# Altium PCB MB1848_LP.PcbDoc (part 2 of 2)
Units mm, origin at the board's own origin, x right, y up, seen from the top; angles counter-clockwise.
Board outline 61.5 x 34 mm, 4 copper layers (Top Layer, MidLayer 1, MidLayer 2, Bottom Layer), stack 1.035 mm thick; 72 components, 64 nets, 238 pads, 1060 vias.
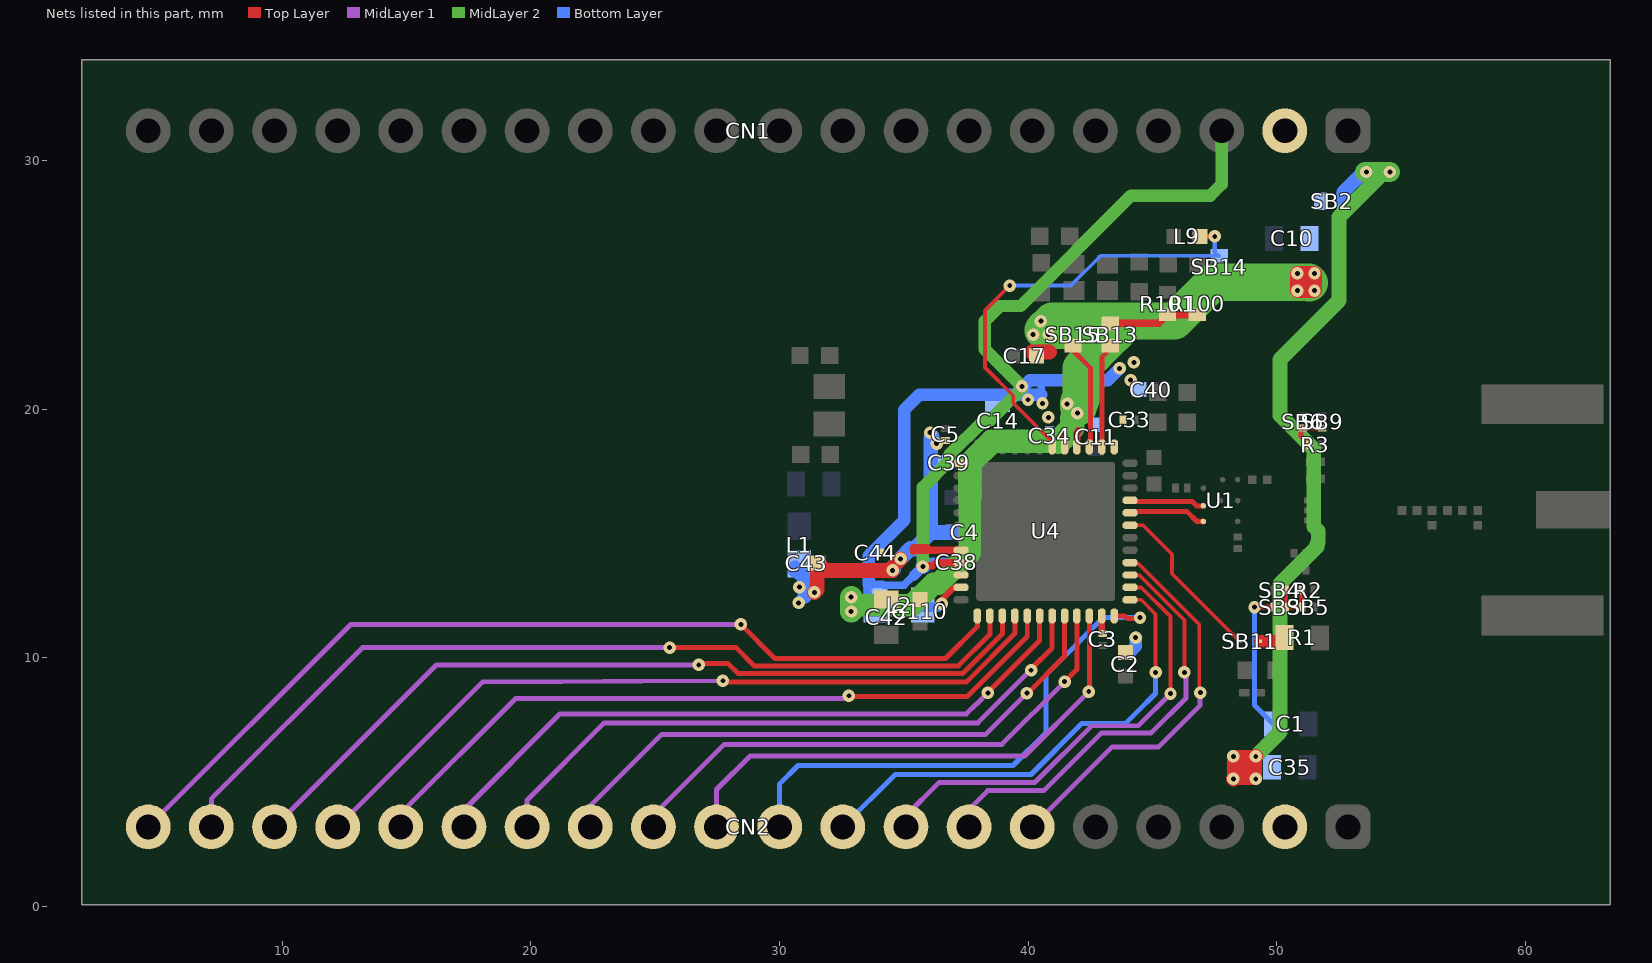
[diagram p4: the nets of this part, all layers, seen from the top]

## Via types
v1: diameter 0.4, hole 0.2, Top Layer to Bottom Layer, 477 vias
v2: diameter 0.65, hole 0.2, Top Layer to Bottom Layer, 317 vias
v3: diameter 0.5, hole 0.2, Top Layer to Bottom Layer, 189 vias
v4: diameter 0.4, hole 0.2, Top Layer to Bottom Layer, tented both sides, 77 vias

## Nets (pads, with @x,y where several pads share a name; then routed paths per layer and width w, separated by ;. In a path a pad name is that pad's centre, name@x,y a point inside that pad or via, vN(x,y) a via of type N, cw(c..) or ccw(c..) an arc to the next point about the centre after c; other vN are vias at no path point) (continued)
NetCN2_6: CN2.6 U4.16 | length 15.9
  Top Layer w0.15: U4.16@44.099,13.824 44.143,13.78 44.437,13.78 46.883,11.333 v3@46.883,8.632
  Top Layer w0.2: v3@46.883,8.632 46.883,8.551 46.903,8.532 46.903,8.571 v3(46.923,8.592)
  MidLayer 1 w0.2: CN2.6@40.163,3.192 43.386,6.414 45.248,6.414 46.903,8.07 v3@46.903,8.552
NetCN2_7: CN2.7 U4.15 | length 17.4
  Top Layer w0.15: U4.15@44.099,13.324 44.114,13.309 44.478,13.309 46.283,11.504 v3(46.283,9.41)
  MidLayer 1 w0.2: CN2.7@37.623,3.192 37.623,3.902 38.368,4.646 40.628,4.646 42.941,6.959 44.934,6.959 46.346,8.371 46.346,9.348 v3(46.283,9.41)
NetCN2_8: CN2.8 U4.14 | length 18.3
  Top Layer w0.15: U4.14@44.099,12.824 44.551,12.824 45.723,11.651 v3(45.723,8.552)
  MidLayer 1 w0.2: CN2.8@35.083,3.192 35.083,3.646 36.42,4.983 40.274,4.983 42.549,7.259 44.431,7.259 v3(45.723,8.552)
NetCN2_9: CN2.9 U4.13 | length 19.3
  Top Layer w0.15: U4.13@44.099,12.324 44.543,12.324 45.123,11.743 v3(45.123,9.41)
  Bottom Layer w0.2: CN2.9@32.543,3.192 34.653,5.301 36.314,5.301 cw(c36.349,5.054) 36.384,5.301 40.111,5.301 42.165,7.354 43.923,7.354 44.372,7.804 45.123,8.555 v3(45.123,9.41)
NetCN2_10: CN2.10 U4.12 | length 21.5
  Top Layer w0.2: U4.12@43.461,11.677 43.878,11.677 43.99,11.565 44.451,11.565 v3(44.498,11.611)
  Bottom Layer w0.2: CN2.10@30.003,3.192 30.003,4.927 30.74,5.663 39.39,5.663 40.722,6.996 40.722,9.311 43.023,11.611 v3(44.498,11.611)
NetCN2_11: CN2.11 U4.10 | length 21.2
  Top Layer w0.2: v3(42.435,8.63) 42.461,8.657 U4.10@42.461,11.677
  MidLayer 1 w0.2: CN2.11@27.463,3.192 27.463,4.695 28.814,6.046 39.85,6.046 v3(42.435,8.63)
NetCN2_12: CN2.12 U4.9 | length 22.1
  Top Layer w0.2: v3(41.466,9.032) 41.961,9.528 U4.9@41.961,11.677
  MidLayer 1 w0.2: CN2.12@24.923,3.192 24.923,3.659 27.774,6.509 38.942,6.509 v3(41.466,9.032)
NetCN2_13: CN2.13 U4.8 | length 24
  Top Layer w0.2: v3(39.943,8.572) 39.983,8.572 41.461,10.05 U4.8@41.461,11.677
  MidLayer 1 w0.2: CN2.13@22.383,3.192 22.383,4.038 25.26,6.914 38.286,6.914 v3(39.943,8.572)
NetCN2_14: CN2.14 U4.7 | length 26
  Top Layer w0.2: v3(40.115,9.492) 40.115,9.544 40.961,10.39 U4.7@40.961,11.677
  MidLayer 1 w0.2: CN2.14@19.843,3.192 19.843,4.27 22.953,7.379 37.971,7.379 v3@40.099,9.508
NetCN2_15: CN2.15 U4.6 | length 28.2
  Top Layer w0.15: U4.6@40.421,11.637 U4.6@40.461,11.677 U4.6@40.461,11.427
  Top Layer w0.2: v3@38.363,8.532 v3@38.403,8.572 ; v3@38.443,8.572 v3@38.403,8.572 ; U4.6@40.463,11.752 40.463,11.677 40.463,11.637 40.463,11.427 40.463,10.692 38.363,8.592 v3(38.373,8.582) 38.383,8.572 v3@38.403,8.572
  MidLayer 1 w0.2: CN2.15@17.303,3.192 17.303,3.872 21.168,7.737 37.514,7.737 37.91,8.133 37.925,8.133 v3(38.373,8.582)
NetCN2_16: CN2.16 U4.5 | length 29.5
  Top Layer w0.2: v3@32.791,8.435 37.55,8.435 39.944,10.83 39.961,10.83 U4.5@39.961,11.677
  MidLayer 1 w0.2: CN2.16@14.763,3.192 14.763,3.738 19.383,8.357 32.674,8.357 v3(32.784,8.467)
NetCN2_17: CN2.17 U4.4 | length 31.2
  Top Layer w0.2: v3(27.722,9.069) 27.779,9.012 27.988,9.012 ; 27.989,9.011 37.503,9.011 39.461,10.97 U4.4@39.461,11.677
  MidLayer 1 w0.2: CN2.17@12.223,3.192 18.058,9.027 v3(27.722,9.069)
NetCN2_18: CN2.18 U4.3 | length 33.5
  Top Layer w0.2: v3(26.749,9.709) 26.794,9.755 27.934,9.755 28.324,9.365 32.297,9.365 32.299,9.367 37.375,9.367 38.961,10.953 U4.3@38.961,11.677
  MidLayer 1 w0.2: CN2.18@9.683,3.192 16.199,9.707 v3(26.749,9.709)
NetCN2_19: CN2.19 U4.2 | length 36.5
  Top Layer w0.2: v3(25.577,10.398) 28.25,10.398 28.983,9.665 32.173,9.665 32.175,9.667 37.19,9.667 38.461,10.938 U4.2@38.461,11.677
  MidLayer 1 w0.2: CN2.19@7.143,3.192 7.143,4.321 13.22,10.398 v3(25.577,10.398)
NetCN2_20: CN2.20 U4.1 | length 38.3
  Top Layer w0.2: v3(28.438,11.338) 29.811,9.965 32.049,9.965 32.05,9.967 33.169,9.967 ; 33.215,9.972 cw(c33.169,10.167) 33.169,9.967 ; U4.1@37.954,11.677 37.954,11.245 36.676,9.967 33.169,9.967
  MidLayer 1 w0.2: CN2.20@4.603,3.192 12.739,11.328 28.428,11.328 v3(28.438,11.338)
NetL2_2: L2.2 U4.47 | length 2
  Top Layer w0.25: v3(36.523,12.172) 36.523,12.331 37.015,12.824 U4.47@37.302,12.824
  Bottom Layer w0.4: L2.2@35.776,12.032 36.366,12.032 v3@36.543,12.209
NetL9_2: L9.2 SB14.1 U4.30 | length 18.4
  Top Layer w0.15: v3(39.258,24.965) 38.26,23.967 38.26,21.665 39.394,20.531 39.394,20.247 40.961,18.68 U4.30@40.961,18.474
  Top Layer w0.2: L9.2@46.963,26.942 v3(47.503,26.942)
  Bottom Layer w0.15: v3(39.258,24.965) 41.71,24.965 42.914,26.169 SB14.1@47.678,26.169 cw(c47.678,26.343) SB14.1@47.503,26.343
  Bottom Layer w0.2: SB14.1@47.503,26.343 v3(47.503,26.942)
NetR1_2: R1.2 SB11.1 | length 1
  Top Layer w0.5: SB11.1@49.328,10.661 50.172,10.661 R1.2@50.303,10.792
NetR2_2: R2.2 SB3.2 SB4.2 SB5.2 | length 2
  Top Layer w0.2: SB4.2@50.357,12.718 SB3.2@50.357,12.034 50.359,12.035 SB5.2@51.022,12.035 R2.2@51.022,12.72
NetR3_2: R3.2 SB6.2 SB9.2 | length 1.8
  Top Layer w0.2: SB6.2@51.041,19.24 SB6.2@50.986,19.24 ; SB6.2@51.041,19.27 SB6.2@51.029,19.283 ; R3.2@51.312,18.566 50.976,18.901 50.976,19.23 SB6.2@50.986,19.24 ; SB9.2@51.832,19.24 51.072,19.24 SB6.2@51.029,19.283 ; SB6.2@50.986,19.24 SB6.2@51.029,19.283
NetR100_1: R100.1 R101.1 SB13.2 | length 3.8
  Top Layer w0.2: SB13.2@43.303,23.442 SB13.2@43.403,23.542
  Top Layer w0.3: SB13.2@43.303,23.442 45.253,23.442 R101.1@45.603,23.792 R100.1@46.803,23.792
NetSB11_2: SB11.2 U4.19 | length 6.8
  Top Layer w0.15: U4.19@44.099,15.324 44.614,15.324 45.783,14.155 45.783,13.372 48.163,10.992 48.172,10.992 SB11.2@48.503,10.661
NetSB13_1: SB13.1 U4.26 | length 4.1
  Top Layer w0.2: U4.26@42.961,18.474 42.961,22.089 SB13.1@43.303,22.431
NetSB14_2: SB14.2
NetSB15_1: SB15.1 U4.27 | length 4.2
  Top Layer w0.2: SB15.1@41.803,22.352 42.513,21.642 42.513,18.525 U4.27@42.461,18.474
RFI_N: U1.3 U4.21 | length 3
  Top Layer w0.2: U4.21@44.145,16.286 46.59,16.286 46.771,16.105 U1.3@47.048,16.105
RFI_P: U1.2 U4.20 | length 3.1
  Top Layer w0.2: U4.20@44.133,15.873 46.395,15.873 46.791,15.477 U1.2@47.028,15.476
  Top Layer w0.22: U1.2@47.028,15.476 U1.2@47.035,15.469
VDD: C1.2 C2.2 C3.2 C4.2 C5.2 C35.2 C39.1 C43.2 C44.2 CN2.2 L1.1 SB2.1 SB3.1 U4.11 U4.37 U4.44 | length 56.9
  Top Layer w0.2: v3@49.11,12.036 49.112,12.034 SB3.1@49.877,12.034
  Top Layer w0.254: C3.2@42.963,11.072 U4.11@42.963,11.635
  Top Layer w0.3: 35.373,14.279 35.418,14.324 ; 35.817,14.384 35.948,14.384 36.009,14.324 U4.44@37.302,14.324
  Top Layer w0.4: 35.413,14.367 35.931,14.367
  Top Layer w0.5: v3(48.253,5.125) v3(48.253,6.025) v3(49.153,6.025) v3(49.153,5.125) v3(48.253,5.125)
  Top Layer w0.6: v3(31.401,12.621) 31.514,12.735 31.514,13.372 ; C43.2@31.546,13.802 31.839,13.51 v3(34.549,13.51) 34.549,13.649 v3(34.87,13.971) ; v3(48.253,5.125) v3(49.153,6.025)
  MidLayer 2 w0.6: v3(49.153,6.025) 50.131,7.004 50.131,12.972 51.611,14.452 51.611,14.578 51.665,14.632 51.665,15.087 51.635,15.117 51.635,15.129 51.486,15.278 51.486,18.388 50.128,19.746 50.128,21.993 52.503,24.368 52.503,27.72 54.097,29.314 54.097,29.535
  MidLayer 2 w0.8: v3@53.546,29.535 v3@54.546,29.535
  Bottom Layer w0.2: v3(49.103,12.034) 49.103,8.085 C1.2@49.856,7.332
  Bottom Layer w0.45: C4.2@36.955,15.035 C4.2@36.968,15.048
  Bottom Layer w0.5: 44.026,10.152 44.321,10.447 v3(44.321,10.802)
  Bottom Layer w0.55: SB2.1@52.668,28.363 52.668,28.719 v3@53.483,29.533
  Bottom Layer w0.6: L1.1@30.614,13.529 30.614,13.604 31.023,13.195 31.023,12.47 ; v3(34.549,13.51) 34.549,13.519 34.592,13.562 34.592,13.693 v3(34.87,13.971) 34.87,13.991 35.266,14.386 ; 35.413,14.367 36.081,15.035 ; v3@36.134,18.901 36.081,18.848 36.081,15.035 ; C4.2@36.955,15.035 36.081,15.035
  Bottom Layer w0.8: v3(53.602,29.533) v3@54.294,29.533
  other v3: 30.769,12.198 30.795,12.839 36.313,18.604 36.052,19.052 54.544,29.533
VDDPA: C14.1 C33.2 C34.2 C38.1 C40.1 L2.1 U4.25 U4.29 U4.45 | length 51.2
  Top Layer w0.3: v3(35.763,13.658) 35.801,13.696 36.163,13.696 36.291,13.824 U4.45@37.302,13.824 ; U4.29@41.461,18.474 41.461,18.826
  MidLayer 2 w0.4: v3@39.606,20.909 v3(39.751,20.909)
  MidLayer 2 w0.5: v3(35.763,13.658) 35.763,16.847 36.821,17.905 36.821,18.146 38.196,19.521 38.437,19.521 39.751,20.835 v3(39.751,20.909) 38.26,22.4 38.26,22.582 38.256,22.585 38.256,23.082 38.26,23.086 38.26,23.541 38.863,24.144 39.701,24.144 44.136,28.58 47.322,28.58 47.783,29.041 47.783,31.192
  Bottom Layer w0.3: L2.1@33.851,12.112 33.552,12.411 33.552,12.947 33.585,12.947 34.156,12.947 34.193,12.91 35.006,12.91 35.006,12.924 35.412,13.329 ; v3@35.712,13.658 v3(35.763,13.658) ; v3@35.782,13.677 v3(35.763,13.658) ; v3@35.817,13.658 v3(35.763,13.658) ; 40.531,20.579 40.531,21.038 40.573,21.08
  Bottom Layer w0.4: 35.412,13.329 35.412,13.309 35.375,13.273 35.378,13.273 v3(35.763,13.658) ; v3@35.782,13.677 35.942,13.837 C38.1@36.742,13.837
  Bottom Layer w0.5: 33.585,12.947 33.585,14.099 35.01,15.524 35.01,19.959 35.616,20.565 36.145,20.565 36.159,20.579 40.531,20.579 ; v3@39.804,20.899 40.068,21.163 43.206,21.163 v3(43.674,21.631)
  Bottom Layer w0.6: v3(35.763,13.658) v3@35.782,13.677
  other v3: 40.809,19.664 40.576,20.228 39.991,20.373 44.118,21.161 44.247,21.875
VDDRF: C10.1 C11.1 C17.1 C42.1 C110.1 CN1.2 SB2.2 U4.28 U4.46 | length 37.8
  Top Layer w0.3: U4.46@37.302,13.324 U4.46@37.312,13.324 ; U4.28@41.961,18.474 41.961,19.033 42.005,19.077 42.005,19.131
  Top Layer w0.6: C17.1@40.152,22.3 40.852,22.3 ; v3(50.823,25.454) v3(51.515,25.454) ; v3@50.823,25.455 v3(50.823,24.764) ; 51.312,25.253 v3(50.823,24.764) ; v3@51.515,25.455 v3(51.515,24.764) v3(50.823,24.764)
  MidLayer 2 w0.9: v3(32.877,11.854) v3(32.877,12.434) ; 33.153,12.112 35.332,12.112 36.192,12.972 36.393,12.972 37.646,14.224 37.646,16.448
  MidLayer 2 w0.95: 37.646,16.448 37.646,16.904 ; 37.646,17.12 37.646,17.804 38.538,18.696 41.21,18.696
  MidLayer 2 w1: 41.21,18.696 41.222,18.696 41.236,18.709 41.238,18.709 41.269,18.741 41.278,18.741 41.293,18.756 41.295,18.756 41.752,19.213 41.752,19.235 41.769,19.252 41.769,19.625
  MidLayer 2 w1.5: v3@42.019,20.079 42.019,20.26 42.123,20.364 42.123,21.635 42.738,22.25 42.738,22.26 43.383,22.905 43.394,22.905 43.653,23.164 40.593,23.164 40.966,23.537 45.882,23.537 47.441,25.096 51.28,25.096 51.3,25.076
  Bottom Layer w0.6: CN1.2@50.323,31.192 CN1.2@50.323,31.414
  other v3: 41.98,19.836 41.568,20.206 40.196,22.994 40.821,22.994 40.507,23.531
pads on no net: U4.23
copper on no net: | length 1464.4
  Top Layer w0.381: 94.787,1.818 105.199,1.818 128.814,1.818 158.016,1.818 174.522,1.818 188.996,1.818 ; 94.787,4.866 105.199,4.866 128.814,4.866 158.016,4.866 174.522,4.866 188.996,4.866 ; 94.787,7.914 105.199,7.914 128.814,7.914 158.016,7.914 174.522,7.914 188.996,7.914 ; 94.787,10.962 105.199,10.962 128.814,10.962 158.016,10.962 174.522,10.962 188.996,10.962 ; 94.787,14.01 105.199,14.01 128.814,14.01 158.016,14.01 174.522,14.01 188.996,14.01 ; 94.787,17.058 105.199,17.058 128.814,17.058 158.016,17.058 174.522,17.058 188.996,17.058 ; 94.787,20.106 105.199,20.106 128.814,20.106 158.016,20.106 174.522,20.106 188.996,20.106 ; 94.787,23.154 105.199,23.154 128.814,23.154 158.016,23.154 174.522,23.154 188.996,23.154 ; 94.787,26.202 105.199,26.202 128.814,26.202 158.016,26.202 174.522,26.202 188.996,26.202 ; 94.787,29.25 105.199,29.25 128.814,29.25 158.016,29.25 174.522,29.25 188.996,29.25 ; 94.787,32.298 188.996,32.298 ; 105.199,35.346 105.199,-1.23 ; 128.814,35.346 128.814,-1.23 ; 158.016,35.346 158.016,-1.23 ; 174.522,35.346 174.522,-1.23 ; 105.199,-1.23 128.814,-1.23 ; 105.199,-1.23 94.787,-1.23 94.787,35.346 188.996,35.346 188.996,-1.23 174.522,-1.23 ; 128.814,-1.23 158.016,-1.23 ; 158.016,-1.23 174.522,-1.23
  Bottom Layer w0.15: 32.543,31.192 32.543,28.586 36.637,24.492 42.065,24.492 43.343,25.77 46.549,25.77 47.051,25.269 47.678,25.269

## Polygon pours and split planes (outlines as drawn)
VDD on MidLayer 2 "NONET_L-01_P-001" (solid, pour order 33): 51.542,1.922 51.542,5.686 ccw(c50.812,5.686) 51.328,6.202 46.658,10.872 ccw(c46.248,10.462) 46.248,11.042 42.724,11.042 32.958,11.042 cw(c32.958,12.079) 31.921,12.079 31.921,12.256 cw(c32.654,12.256) 32.654,12.989 34.084,12.989 ccw(c34.084,14.226) 35.322,14.227 35.322,17.276 36.578,18.532 ccw(c36.29,18.82) 36.578,19.108 36.009,19.677 ccw(c35.531,19.2) 35.052,19.677 29.498,14.124 ccw(c30.249,13.373) 29.187,13.373 29.187,8.108 ccw(c29.931,8.108) 29.405,7.582 30.795,6.192 ccw(c31.287,6.685) 31.287,5.988 44.296,5.988 cw(c44.296,4.947) 45.027,5.689 46.064,4.669 ccw(c46.339,4.948) 46.339,4.556 48.082,4.556 cw(c48.082,4.069) 48.451,4.386 48.77,4.015 cw(c48.282,3.595) 48.926,3.595 48.926,1.922
GND on MidLayer 2 "TOP_LAYER_GND" (solid, remove dead copper, pour order 34): 1.97,34.244 63.467,34.244 63.467,0.056 1.97,0.056
GND on Top Layer "TOP_LAYER_GND" (solid, remove dead copper, pour order 30): 1.922,34.244 63.467,34.244 63.467,0.056 1.922,0.056
GND on MidLayer 1 "NONET_L-01_P-001" (solid, pour order 31): 1.932,0.056 63.43,0.056 63.43,34.269 1.932,34.269
GND on Bottom Layer "GND_L04_P035" (solid, remove dead copper, pour order 35): 1.97,34.244 63.467,34.244 63.467,0.056 1.97,0.056

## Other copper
Top Layer:
  region net VDD: 35.213,14.02 35.318,14.02 ccw(c35.318,14.586) 35.718,14.186 35.413,14.367
  region net VDDRF: 32.724,12.804 34.881,12.804 ccw(c34.881,15.615) 36.142,13.102 36.722,13.393 cw(c37.048,12.745) 37.048,13.471 37.391,13.471 37.391,13.181 37.162,13.181 ccw(c37.161,12.624) 36.82,13.064 35.371,11.989 33.773,11.989 33.547,11.675 cw(c33.23,11.902) 33.23,11.512 32.706,11.512 cw(c32.706,11.661) 32.558,11.661 32.558,12.637 cw(c32.724,12.637)
  region net VDD: 31.245,11.887 30.68,11.887 cw(c30.68,12.141) 30.426,12.141 30.426,12.958 cw(c30.745,12.958) 30.745,13.277 31.439,13.277 cw(c31.439,12.967) 31.75,12.967 31.75,12.569 cw(c31.323,12.569) 31.625,12.268
  region net VDDPA: 39.521,21.078 ccw(c39.748,20.93) 39.556,20.739 39.64,20.655 39.713,20.366 ccw(c40.048,20.451) 39.81,20.199 41.372,18.72 41.608,18.72 41.608,18.848 ccw(c41.039,18.849) 41.441,19.252 41.305,19.387 cw(c41.535,19.617) 41.21,19.617 41.21,19.649 41.21,19.733 ccw(c40.111,19.734) 40.888,20.511 40.354,21.045 ccw(c39.909,20.601) 39.909,21.229 39.799,21.229 ccw(c39.799,20.897)
  region net VDDRF: 41.806,18.772 41.806,19.207 ccw(c40.838,19.207) 41.523,19.892 41.355,20.059 cw(c41.475,20.179) 41.306,20.179 41.306,20.26 cw(c41.444,20.26) 41.346,20.358 41.421,20.433 cw(c41.502,20.352) 41.502,20.467 41.637,20.467 cw(c41.638,20.153) 41.86,20.375 42.191,20.044 cw(c42.072,19.925) 42.24,19.925 42.24,19.116 cw(c41.739,19.116) 42.177,18.872 42.121,18.772
  region net VDDRF: 41.409,20.003 41.36,20.053 cw(c41.515,20.209) 41.295,20.209 41.295,20.279 ccw(c40.858,20.279) 41.167,20.588 40.045,21.71 cw(c40.518,22.183) 39.849,22.183 39.849,23.415 cw(c40.324,23.415) 40.324,23.89 40.747,23.89 cw(c40.747,23.42) 41.216,23.42 41.216,22.002 ccw(c42.068,22.002) 41.466,21.399 41.878,20.988 cw(c41.528,20.637) 42.023,20.637 42.023,19.836
  region net VDD: 42.828,10.826 42.828,11.114 43.233,11.114 44.333,11.114 cw(c44.333,10.792) 44.656,10.792 44.656,10.039 cw(c43.955,10.038) 44.64,9.889 43.605,9.889 43.603,10.456 ccw(c43.3,10.455) 43.418,10.734 43.2,10.826
  region net VDD: 37.302,17.68 36.755,17.68 35.824,18.61 cw(c36.047,18.834) 35.731,18.834 35.731,19.206 cw(c35.927,19.206) 35.927,19.402 36.107,19.402 cw(c36.107,19.187) 36.322,19.187 36.322,18.994 36.438,18.878 36.866,18.878 37.24,18.504 cw(c37.091,18.355) 37.302,18.355
  region net VDDPA: 43.313,18.389 43.313,21.431 cw(c43.929,21.431) 43.521,21.893 43.751,22.096 cw(c43.928,21.896) 43.928,22.163 44.627,22.163 cw(c44.627,22.051) 44.739,22.051 44.739,21.718 cw(c44.087,21.718) 44.613,21.332 44.416,21.063 ccw(c44.563,20.773) 44.273,20.92 44.031,20.538 43.96,19.832 43.96,19.337 43.615,18.992 43.615,18.398
  pour cut-out: 44.873,18.925 44.86,18.938 44.672,19.056 44.672,19.139 44.86,19.327 46.909,19.327 46.909,18.938 44.873,18.938 44.848,18.964
  pour cut-out: 44.882,19.798 44.869,19.811 44.681,19.928 44.681,20.012 44.869,20.2 46.917,20.2 46.917,19.811 44.882,19.811 44.856,19.837
  pour cut-out: 43.96,19.832 44.16,19.832 44.166,19.838 44.166,19.283 44.014,19.283 43.96,19.337
  region net GND: 43.503,25.142 45.203,25.142 45.403,24.942 45.403,24.342 44.903,24.342 43.803,24.342 43.703,24.442 43.503,24.442
  pour cut-out: 31.343,20.372 32.643,20.372 32.643,19.872 31.343,19.872
  pour cut-out: 46.003,26.242 46.503,26.242 46.503,25.542 46.403,25.442 46.003,25.442
  pour cut-out: 46.203,27.342 46.603,27.342 46.603,26.542 46.203,26.542
  pour cut-out: 40.903,27.342 41.403,27.342 41.403,26.442 41.303,26.542 40.903,26.542
  pour cut-out: 49.266,9.954 49.328,9.892 49.703,9.892 49.703,9.092 49.203,9.092
  pour cut-out: 37.523,18.232 43.843,18.232 43.783,18.172 43.783,11.952 38.123,11.952 38.123,12.532 37.523,12.532
  region net VDD: 33.963,14.397 34.113,14.547 35.295,14.547 35.566,14.276 34.597,13.307 33.963,13.307
  region net NetC28_2: 58.443,15.919 59.132,16.688 60.782,16.688 60.782,15.194 59.093,15.194
  pour cut-out: 41.863,18.692 41.863,20.892 39.543,23.212 39.543,27.692 40.703,27.692 47.603,27.692 47.603,25.992 47.603,23.192 47.103,22.592 44.963,22.592 43.423,21.052 43.423,19.012 43.103,18.692
  pour cut-out: 45.16,17.299 47.516,17.299 47.516,15.012 45.16,15.012
  pour cut-out: 44.399,17.866 46.864,17.866 46.864,17.297 44.399,17.297
  region net NetC19_2: 49.012,17.013 48.858,17.013 48.426,17.158 48.858,17.303 49.012,17.303
  region net NetC25_1: 54.961,15.744 54.837,15.744 54.328,15.919 54.838,16.094 54.961,16.094
  region net NetC19_1: 49.711,17.333 49.83,17.333 50.166,17.076 49.801,16.983 49.711,16.983
  pour cut-out: 63.516,14.184 59.037,14.184 59.037,17.712 63.516,17.712
  pour cut-out: 58.536,16.273 59.036,17.704 59.036,16.286 59.024,16.273
  pour cut-out: 58.533,15.583 59.046,15.583 59.046,14.157 58.52,15.596
  text "Layer" at 96.565,33.06 h1.52
  text "Name" at 106.977,33.06 h1.52
  text "Material" at 130.592,33.06 h1.52
  text "Thickness" at 159.794,33.06 h1.52
  text "Constant" at 176.3,33.06 h1.52
  text "Top Overlay" at 106.977,30.012 h1.52
  text "Top Solder" at 106.977,26.964 h1.52
  text "Solder Resist" at 130.592,26.964 h1.52
  text "0.39mil" at 159.794,26.964 h1.52
  text "3.5" at 176.3,26.964 h1.52
  text "1" at 96.565,23.916 h1.52
  text "Top Layer" at 106.977,23.916 h1.52
  text "1.38mil" at 159.794,23.916 h1.52
  text "Dielectric 2" at 106.977,20.868 h1.52
  text "1 x 2116 + 1 x 106" at 130.592,20.868 h1.52
  text "6.30mil" at 159.794,20.868 h1.52
  text "3.7" at 176.3,20.868 h1.52
  text "2" at 96.565,17.82 h1.52
  text "MidLayer 1" at 106.977,17.82 h1.52
  text "0.69mil" at 159.794,17.82 h1.52
  text "Dielectric 1" at 106.977,14.772 h1.52
  text "FR-4" at 130.592,14.772 h1.52
  text "24.02mil" at 159.794,14.772 h1.52
  text "5" at 176.3,14.772 h1.52
  text "3" at 96.565,11.724 h1.52
  text "MidLayer 2" at 106.977,11.724 h1.52
  text "0.69mil" at 159.794,11.724 h1.52
  text "Dielectric 3" at 106.977,8.676 h1.52
  text "1 x 2116 + 1 x 106" at 130.592,8.676 h1.52
  text "6.30mil" at 159.794,8.676 h1.52
  text "3.7" at 176.3,8.676 h1.52
  text "4" at 96.565,5.628 h1.52
  text "Bottom Layer" at 106.977,5.628 h1.52
  text "1.38mil" at 159.794,5.628 h1.52
  text "Bottom Solder" at 106.977,2.58 h1.52
  text "Solder Resist" at 130.592,2.58 h1.52
  text "0.39mil" at 159.794,2.58 h1.52
  text "3.5" at 176.3,2.58 h1.52
  text "Bottom Overlay" at 106.977,-0.468 h1.52
  text ".Layer_Name" at 11.222,-22.076 h3
  text ".GTL" at 52.917,-22.076 h3
MidLayer 1:
  pour cut-out: 63.522,12.744 59.043,12.744 59.043,19.094 63.522,19.094
  pour cut-out: 41.913,18.655 41.913,20.855 39.593,23.175 39.593,27.655 40.753,27.655 47.653,27.655 47.653,25.955 47.653,23.155 47.153,22.555 45.013,22.555 43.473,21.015 43.473,18.975 43.153,18.655
  text ".Layer_Name" at 11.222,-22.076 h3
  text ".G1" at 52.917,-22.076 h3
MidLayer 2:
  region net VDDPA: 39.905,21.434 40.714,20.626 cw(c39.735,19.647) 41.119,19.647 41.119,19.597 cw(c40.886,19.597) 40.996,19.391 cw(c40.899,19.455) 40.899,19.339 40.448,19.339 39.11,20.677 cw(c39.227,20.794) 39.11,20.911 39.632,21.434 cw(c39.769,21.298)
  region net VDDPA: 39.151,20.877 38.113,19.339 40.743,19.339
  pour cut-out: 41.756,18.563 41.756,20.763 39.436,23.083 39.436,27.563 40.596,27.563 47.496,27.563 47.496,25.863 47.496,23.063 46.996,22.463 44.856,22.463 43.316,20.923 43.316,18.883 42.996,18.563
  text ".Layer_Name" at 11.222,-22.076 h3
  text ".G2" at 52.917,-22.076 h3
Bottom Layer:
  region net VDD: 31.245,11.887 30.68,11.887 cw(c30.68,12.141) 30.426,12.141 30.426,13.277 31.439,13.277 cw(c31.439,12.967) 31.75,12.967 31.75,12.569 cw(c31.323,12.569) 31.625,12.268
  region net VDDPA: 38.27,19.854 38.27,20.405 39.065,21.2 cw(c39.583,20.683) 39.583,21.415 40.842,21.415 40.842,20.509 ccw(c40.93,20.509) 40.93,20.42 cw(c40.93,20.264) 41.086,20.264 41.086,19.113 cw(c41.004,19.113) 41.004,19.03 40.656,19.03 cw(c40.656,19.328) 40.358,19.328 40.358,19.777 ccw(c40.28,19.777) 40.28,19.854
  region net VDDRF: 41.417,20.471 41.662,20.471 cw(c41.662,20.299) 41.81,20.387 41.919,20.204 ccw(c42.079,20.299) 42.079,20.114 42.571,20.114 cw(c42.571,19.843) 42.763,20.035 42.918,19.879 cw(c42.657,19.618) 43.027,19.617 43.027,19.061 42.237,19.057 41.33,20.082 cw(c41.463,20.15) 41.313,20.15 41.313,20.367 cw(c41.417,20.367)
  region net VDD: 36.633,17.558 36.633,18.169 cw(c36.815,18.169) 36.686,18.297 37.092,18.703 37.292,18.703 37.301,18.712 37.301,19.061 37.284,19.077 37.185,19.077 36.887,19.376 ccw(c36.702,19.191) 36.702,19.452 35.994,19.452 ccw(c35.994,19.281) 35.822,19.281 35.822,17.751 ccw(c36.033,17.75) 36.034,17.54 36.619,17.545 ccw(c36.619,17.558)
  region net VDD: 50.167,5.585 50.167,7.842 48.247,7.842 47.469,7.063 47.469,5.49 49.198,3.764 ccw(c50.253,3.256) 50.75,4.317 cw(c51.644,5.496)
  region net VDDRF: 50.151,24.323 50.151,25.504 50.943,25.919 50.926,27.113 ccw(c48.28,27.113) 50.151,28.984 49.543,29.591 cw(c50.045,30.093) 49.336,30.093 49.336,31.767 cw(c49.776,31.767) 49.776,32.207 50.943,32.207 cw(c50.943,31.816) 51.335,31.816 51.335,29.962 ccw(c52.431,29.962) 51.656,29.186 cw(c50.63,28.16) 52.081,28.16 52.081,24.323
  region net VDDRF: 42.453,21.881 42.453,23.117 41.95,23.621 ccw(c41.093,22.764) 41.093,23.976 40.333,23.976 ccw(c40.333,23.521) 39.878,23.521 39.878,22.765 ccw(c40.762,22.765) 40.762,21.881 41.721,21.881
  pour cut-out: 37.243,14.592 36.503,14.592 36.443,14.532 36.443,13.552 37.223,13.552 37.243,13.532
  pour cut-out: 34.383,12.712 35.183,12.712 35.183,11.312 34.383,11.312
  region net VDDPA: 41.083,20.241 41.074,20.498 41.263,20.66 41.867,20.66 42.216,20.312 44.566,20.312 44.752,20.498 44.752,21.057 44.752,22.111 44.549,22.315 43.99,22.315 43.99,22.298 43.414,21.721 42.802,21.119 42.776,21.145 40.746,21.145 40.604,21.003 40.622,20.986 40.622,20.472 40.666,20.472 40.87,20.268 41.1,20.268
  text ".GBL" at 41.714,-22.108 h3
  text ".Layer_Name" at 83.028,-22.108 h3

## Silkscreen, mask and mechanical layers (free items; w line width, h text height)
Top Overlay:
  region: 6.873,23.491 6.873,10.515 16.522,10.515 16.522,23.491
  lines w0.15: 3.89,33.289 5.197,33.289 ; 4.044,33.627 5.044,33.627 ; 4.294,33.965 4.794,33.965 ; 4.539,32.277 4.539,33.287 ; 39.515,33.254 40.821,33.254 ; 39.668,33.592 40.668,33.592 ; 39.918,33.93 40.418,33.93 ; 40.163,32.242 40.163,33.252 ; 44.592,33.261 45.899,33.261 ; 44.746,33.598 45.746,33.598 ; 44.996,33.936 45.496,33.936 ; 45.241,32.248 45.241,33.259 ; 47.128,33.243 48.435,33.243 ; 47.281,33.581 48.281,33.581 ; 47.531,33.919 48.031,33.919 ; 47.777,32.231 47.777,33.241 ; 52.224,33.272 53.531,33.272 ; 52.377,33.61 53.377,33.61 ; 52.627,33.947 53.127,33.947 ; 52.873,32.259 52.873,33.27 ; 52.898,5.433 54.204,5.433 ; 53.051,5.771 54.051,5.771 ; 53.301,6.109 53.801,6.109 ; 53.546,4.421 53.546,5.431
  text "PA15" at 11.146,32.62 h1
  text "PA14" at 13.835,32.62 h1
  text "PA13" at 16.517,32.62 h1
  text "PA12" at 19.201,32.62 h1
  text "PA11" at 21.879,32.62 h1
  text "PA10" at 24.439,32.62 h1
  text "PB12" at 27.121,32.62 h1
  text "PB2" at 29.799,32.62 h1
  text "PB0" at 31.98,32.62 h1
  text "VDDRF" at 48.849,32.638 h1
  text "PC13" at 34.165,32.611 h1
  text "VRPA" at 41.673,32.603 h1
  text "MB1848-LP" at 4.446,23.194 h2.5 r270
  text "Notes:" at 17.177,23.194 h1.2 r270
  text "PB3" at 3.788,1.116 h1
  text "PB4" at 6.347,1.119 h1
  text "PB5" at 8.904,1.119 h1
  text "PB6" at 11.468,1.117 h1
  text "PB7" at 14.027,1.119 h1
  text "PB8" at 16.586,1.117 h1
  text "PA0" at 19.147,1.117 h1
  text "PA1" at 21.704,1.116 h1
  text "PA2" at 24.139,1.116 h1
  text "PA3" at 26.692,1.116 h1
  text "PA4" at 29.251,1.119 h1
  text "PA5" at 31.808,1.119 h1
  text "PA6" at 34.372,1.117 h1
  text "PA7" at 36.931,1.119 h1
  text "PA8" at 39.491,1.117 h1
  text "PA9" at 42.051,1.117 h1
  text "NRST" at 44.118,1.123 h1
  text "VDD" at 49.571,1.08 h1
  text ".Layer_Name" at 11.222,-22.076 h3
  text ".GTO" at 52.917,-22.076 h3
Bottom Overlay:
  text "MB1848-LP" at 25.84,7.342 h2.5
  text ".GBO" at 41.714,-22.108 h3
  text ".Layer_Name" at 83.028,-22.108 h3
Top Paste:
  lines w0.5: 12.743,26.712 cw(c14.593,26.712) 14.593,28.562 ; 12.752,9.144 12.752,26.644 ; 12.763,9.212 ccw(c14.613,9.212) 14.613,7.362 ; 14.583,7.332 51.483,7.332 ; 14.583,28.572 51.483,28.572 ; 51.493,28.582 cw(c51.493,26.732) 53.343,26.732 ; 51.533,7.342 ccw(c51.533,9.192) 53.383,9.192 53.383,17.689 ; 53.343,17.689 53.343,26.682
  text ".Layer_Name" at 11.222,-22.076 h3
  text ".GTP" at 52.917,-22.076 h3
Bottom Paste:
  text ".GBP" at 41.714,-22.108 h3
  text ".Layer_Name" at 83.028,-22.108 h3
Top Solder:
  lines w1.5: 53.328,17.416 53.328,19.142 53.328,26.448 ; 53.35,9.106 53.35,10.742 53.35,11.942 53.35,14.335 ; 53.352,9.154 cw(c51.502,9.154) 51.502,7.304 43.525,7.304 21.403,7.304 20.977,7.304 cw(c20.977,9.154) 19.127,9.154 19.127,11.942 19.127,22.742 19.127,26.654 cw(c20.977,26.654) 20.977,28.504 23.803,28.504 49.003,28.504 51.502,28.504 cw(c51.502,26.654) 53.352,26.654
  text ".Layer_Name" at 11.222,-22.076 h3
  text ".GTS" at 52.917,-22.076 h3
Bottom Solder:
  text ".GBS" at 41.714,-22.108 h3
  text ".Layer_Name" at 83.028,-22.108 h3
Mechanical 1:
  lines w0.3: 1.922,34.056 1.922,0.056 63.42,0.056 63.42,34.056 1.942,34.056
Top Assembly:
  text ".Layer_Name" at 11.222,-22.076 h3
  text ".GM2" at 52.917,-22.076 h3
Top Assembly (Mech14):
  rectangle: 46.85,16.963 47.129,17.305
  lines w0.1: 61.884,34.001 61.884,0.101 1.973,0.101 1.973,34.006 61.884,34.006
  text ".Layer_Name" at 11.222,-22.076 h3
  text ".GM14" at 52.917,-22.076 h3
Bottom Assembly (Mech15):
  lines w0.1: 61.884,34.006 61.884,0.106 1.973,0.106 1.973,34.011 61.884,34.011
  text ".GM15" at 41.714,-22.108 h3
  text ".Layer_Name" at 83.028,-22.108 h3
Drill Drawing:
  lines w0.2: 3.193,76.797 32.943,76.797 ; 2.193,44.797 146.943,44.797 146.943,80.297 140.693,80.297 2.193,80.297 2.193,51.047 2.193,44.797 ; 2.943,46.047 5.443,46.047 5.443,48.547 2.943,48.547 2.943,46.047 ; 2.943,55.047 2.943,57.547 5.443,57.547 5.443,55.047 2.943,55.047 ; 41.443,55.047 43.943,55.047 43.943,57.547 41.443,57.547 41.443,55.047 ; 41.443,58.047 43.943,58.047 43.943,60.547 41.443,60.547 41.443,58.047 ; 41.443,61.047 43.943,61.047 43.943,63.547 41.443,63.547 41.443,61.047 ; 41.443,64.047 43.943,64.047 43.943,66.547 41.443,66.547 41.443,64.047 ; 41.443,67.047 43.943,67.047 43.943,69.547 41.443,69.547 41.443,67.047 ; 57.943,55.047 57.943,57.547 60.443,57.547 60.443,55.047 57.943,55.047 ; 57.943,58.047 57.943,60.547 60.443,60.547 60.443,58.047 57.943,58.047 ; 57.943,61.047 57.943,63.547 60.443,63.547 60.443,61.047 57.943,61.047 ; 57.943,64.047 57.943,66.547 60.443,66.547 60.443,64.047 57.943,64.047 ; 57.943,67.047 57.943,69.547 60.443,69.547 60.443,67.047 57.943,67.047 ; 57.943,73.047 60.443,73.047 60.443,75.547 57.943,75.547 57.943,73.047 ; 66.943,49.047 66.943,51.547 69.443,51.547 69.443,49.047 66.943,49.047 ; 76.193,64.047 78.693,64.047 78.693,66.547 76.193,66.547 76.193,64.047 ; 76.193,67.047 78.693,67.047 78.693,69.547 76.193,69.547 76.193,67.047 ; 76.193,73.047 76.193,75.547 78.693,75.547 78.693,73.047 76.193,73.047 ; 92.193,49.047 94.693,49.047 94.693,51.547 92.193,51.547 92.193,49.047 ; 92.193,58.047 94.693,58.047 94.693,60.547 92.193,60.547 92.193,58.047 ; 92.193,61.047 94.693,61.047 94.693,63.547 92.193,63.547 92.193,61.047 ; 92.193,67.047 94.693,67.047 94.693,69.547 92.193,69.547 92.193,67.047 ; 92.193,73.047 92.193,75.547 94.693,75.547 94.693,73.047 92.193,73.047
  lines w0.254: 4.078,94.663 5.771,94.663 4.925,92.97 4.078,94.663 ; 4.078,97.203 4.501,97.203 4.925,96.78 5.348,97.203 5.771,97.203 5.348,97.626 5.771,98.05 5.348,98.05 4.925,98.473 4.501,98.05 4.078,98.05 4.501,97.626 4.078,97.203
  lines w0.381: 2.559,91.827 181.632,91.827 ; 2.559,99.447 181.632,99.447 ; 16.552,88.017 16.552,103.257 ; 32.803,88.017 32.803,103.257 ; 60.481,88.017 60.481,103.257 ; 73.33,88.017 73.33,103.257 ; 91.969,88.017 91.969,103.257 ; 130.058,88.017 130.058,103.257 ; 145.04,88.017 145.04,103.257 ; 163.983,88.017 163.983,103.257 ; 2.559,88.017 181.632,88.017 181.632,103.257 2.559,103.257 2.559,88.017
  text "Symbol" at 4.845,100.59 h1.83
  text "Count" at 17.695,100.59 h1.83
  text "Hole Size" at 33.946,100.59 h1.83
  text "Plated" at 61.624,100.59 h1.83
  text "Hole Type" at 74.473,100.59 h1.83
  text "Drill Layer Pair" at 93.112,100.59 h1.83
  text "Via/Pad" at 131.201,100.59 h1.83
  text "Pad Shape" at 146.183,100.59 h1.83
  text "Template" at 165.126,100.59 h1.83
  text "40" at 17.695,96.78 h1.52
  text "1.000mm (39.37mil)" at 33.946,96.78 h1.52
  text "PTH" at 61.624,96.78 h1.52
  text "Round" at 74.473,96.78 h1.52
  text "Top Layer - Bottom Layer" at 93.112,96.78 h1.52
  text "Pad" at 131.201,96.78 h1.52
  text "(Mixed)" at 146.183,96.78 h1.52
  text "(Mixed)" at 165.126,96.78 h1.52
  text "1060" at 17.695,92.97 h1.52
  text "0.200mm (7.87mil)" at 33.946,92.97 h1.52
  text "PTH" at 61.624,92.97 h1.52
  text "Round" at 74.473,92.97 h1.52
  text "Top Layer - Bottom Layer" at 93.112,92.97 h1.52
  text "Via" at 131.201,92.97 h1.52
  text "Rounded" at 146.183,92.97 h1.52
  text "(Mixed)" at 165.126,92.97 h1.52
  text "1100 Total" at 17.695,89.16 h1.52
  text "PCB SPECIFICATIONS :" at 3.193,77.297 h3
  text "A.   MATERIAL :" at 3.193,73.297 h3
  text "FR-4" at 41.693,73.297 h3
  text "X  TG-170" at 58.193,73.297 h3
  text "TG-150" at 76.443,73.297 h3
  text "TG-140" at 92.443,73.297 h3
  text "B.   MATERIAL FAMILY :" at 3.193,70.297 h3
  text "N/A" at 41.693,70.297 h3
  text "C.   SOLDERMASK COLOR :" at 3.193,67.297 h3
  text "X   GREEN" at 41.693,67.297 h3
  text "BLUE" at 58.193,67.297 h3
  text "RED" at 76.443,67.297 h3
  text "BLACK" at 92.443,67.297 h3
  text "D.   SILKSCREEN COLOR :" at 3.193,64.297 h3
  text "X  WHITE" at 41.693,64.297 h3
  text "YELLOW" at 58.193,64.297 h3
  text "BLACK" at 76.443,64.297 h3
  text "E.   SURFACE FINISH :" at 3.193,61.297 h3
  text "X  ENIG" at 41.693,61.297 h3
  text "IMMERSION SILVER" at 58.193,61.297 h3
  text "IMMERSION TIN" at 92.443,61.297 h3
  text "HASL" at 41.693,58.297 h3
  text "HASL (PB-FREE)" at 58.193,58.297 h3
  text "GOLDEN FINGER" at 92.443,58.297 h3
  text "F.   IMPEDANCE CONTROL :" at 3.193,55.297 h3
  text "NO" at 41.693,55.297 h3
  text "X  YES  (SEE IMPEDANCE TABLE FOR DETAIL INFORMATION)" at 58.193,55.297 h3
  text "G.   THROUGH VIA :" at 3.193,52.297 h3
  text "PLUG THE VIAS WHICH ARE COVERED WITH SOLDERMASK ONE OR TWO SIDE." at 41.693,52.297 h3
  text "PLUG MATERIAL :" at 41.693,49.297 h3
  text "X  SOLDERMASK" at 67.193,49.297 h3
  text "NON-CONDUCTIVE EPOXY." at 92.443,49.297 h3
  text "H.   STACK-UP :" at 3.193,46.297 h3
  text "SEE LAYER STACK-UP SEQUENCE FOR OVERALL THICKNESS." at 41.693,46.297 h3
  text "mils" at 124.746,-17.895 h2.54
  text "mils" at 135.8,-17.895 h2.54
  text ".Layer_Name" at 11.222,-22.076 h3
  text ".DRL" at 52.917,-22.076 h3
  text ".Layer_Name" at 3.289,-27.365 h3
  text ".DRL" at 44.984,-27.365 h3
Mechanical 20:
  circle w0.254: c89.226,-28.797 r1.3
  region: 88.752,-21.56 73.224,-21.56 72.53,-23.336 71.319,-24.561 69.922,-22.701 69.922,-21.05 71.065,-19.653 72.501,-19.274 88.752,-19.274
  region: 74.748,-29.89 63.992,-29.89 64.986,-27.397 72.843,-27.397 73.292,-26.638 75.501,-29.186
  lines w0.254: 64.986,-27.397 73.778,-27.397 70.711,-23.859 cw(c72.515,-21.915) 72.755,-19.274 89.519,-19.274 88.757,-21.56 ; 68.299,-19.027 cw(c70.726,-19.998) 70.962,-17.395 ; 68.339,-18.995 63.992,-29.89 83.315,-29.89 ccw(c83.564,-27.156) 86.113,-28.175 ; 70.078,-22.93 75.501,-29.186 ; 70.332,-22.93 75.637,-29.051 ; 70.332,-22.676 75.637,-28.797 ; 70.43,-21.56 83.423,-21.56 ; 70.459,-22.549 75.764,-28.67 ; 70.586,-22.422 75.891,-28.543 ; 70.713,-22.295 76.018,-28.416 ; 70.84,-22.168 76.145,-28.289 ; 70.895,-20.215 76.2,-26.336 ; 70.963,-17.396 90.413,-17.396 86.114,-28.173 ; 70.967,-22.041 76.218,-28.099 ; 70.967,-21.787 76.272,-27.908 ; 70.967,-21.533 76.272,-27.654 ; 70.967,-20.644 76.272,-26.765 ; 71.094,-21.406 76.399,-27.527 ; 71.094,-21.025 76.399,-27.146 ; 72.466,-27.41 ccw(c72.571,-26.875) 72.869,-26.418 ; 73.553,-21.547 ccw(c73.527,-22.114) 73.196,-22.576 75.561,-25.305 cw(c73.757,-27.249) 74.49,-29.798 ; 79.834,-29.686 82.723,-21.306 ; 80.056,-29.636 82.925,-21.315 ; 80.183,-29.636 83.052,-21.315 ; 80.437,-29.636 83.306,-21.315 ; 80.691,-29.636 83.56,-21.315 ; 80.945,-29.636 83.814,-21.315 ; 81.199,-29.636 84.068,-21.315 ; 81.453,-29.636 84.322,-21.315 ; 81.707,-29.636 84.576,-21.315 ; 81.961,-29.636 84.83,-21.315 ; 82.17,-29.686 85.059,-21.306 ; 85.059,-21.56 88.752,-21.56 ; 88.083,-21.558 88.845,-19.272 ; 88.249,-21.56 89.011,-19.274 ; 88.503,-21.56 89.265,-19.274
  lines w0.3: 2.222,-28.776 62.222,-28.776 ; 2.222,-23.776 62.222,-23.776 ; 2.222,-18.776 62.222,-18.776 ; 42.222,-33.776 42.222,-18.776 ; 62.222,-33.776 62.222,-13.776 ; 79.834,-29.686 82.17,-29.686 ; 2.222,-33.776 2.222,-13.776 92.222,-13.776 92.222,-33.776 2.222,-33.776
  text "Project: '.Board_Name'" at 3.222,-16.992 h3
  text "Layer:" at 3.222,-22.076 h3
  text "Gerber:" at 43.211,-22.076 h3
  text "Variant: '.VariantName'" at 3.222,-27.076 h3
  text "Ref: '.Board_Reference'" at 43.338,-27.076 h3
  text "R" at 88.718,-29.559 h1.52
  text "Date: '.Board_Document_Date'" at 3.222,-32.076 h3
  text "Rev: '.Board_PCB_Revision'" at 43.281,-32.076 h3
Mechanical 21:
  circle w0.254: c5.405,-28.797 r1.3
  region: 19.883,-29.89 30.639,-29.89 29.646,-27.397 21.788,-27.397 21.339,-26.638 19.131,-29.186
  region: 5.88,-21.56 21.407,-21.56 22.101,-23.336 23.312,-24.561 24.709,-22.701 24.709,-21.05 23.566,-19.653 22.13,-19.274 5.88,-19.274
  lines w0.254: 5.366,-19.274 6.128,-21.56 ; 5.62,-19.274 6.382,-21.56 ; 5.786,-19.272 6.548,-21.558 ; 5.874,-21.56 5.112,-19.274 21.876,-19.274 cw(c22.116,-21.915) 23.92,-23.859 20.854,-27.397 29.646,-27.397 ; 5.88,-21.56 9.572,-21.56 ; 8.517,-28.173 4.218,-17.396 23.668,-17.396 ; 8.518,-28.175 ccw(c11.068,-27.156) 11.316,-29.89 30.639,-29.89 26.293,-18.995 ; 9.572,-21.306 12.461,-29.686 ; 9.801,-21.315 12.67,-29.636 ; 10.055,-21.315 12.924,-29.636 ; 10.309,-21.315 13.178,-29.636 ; 10.563,-21.315 13.432,-29.636 ; 10.817,-21.315 13.686,-29.636 ; 11.071,-21.315 13.94,-29.636 ; 11.208,-21.56 24.201,-21.56 ; 11.325,-21.315 14.194,-29.636 ; 11.579,-21.315 14.448,-29.636 ; 11.706,-21.315 14.575,-29.636 ; 11.908,-21.306 14.797,-29.686 ; 18.232,-27.527 23.537,-21.406 ; 18.232,-27.146 23.537,-21.025 ; 18.359,-27.908 23.664,-21.787 ; 18.359,-27.654 23.664,-21.533 ; 18.359,-26.765 23.664,-20.644 ; 18.413,-28.099 23.664,-22.041 ; 18.431,-26.336 23.736,-20.215 ; 18.486,-28.289 23.791,-22.168 ; 18.613,-28.416 23.918,-22.295 ; 18.74,-28.543 24.045,-22.422 ; 18.867,-28.67 24.172,-22.549 ; 18.994,-29.051 24.299,-22.93 ; 18.994,-28.797 24.299,-22.676 ; 19.131,-29.186 24.553,-22.93 ; 20.141,-29.798 cw(c20.874,-27.249) 19.07,-25.305 21.435,-22.576 ccw(c21.105,-22.114) 21.079,-21.547 ; 21.762,-26.418 ccw(c22.06,-26.875) 22.165,-27.411 ; 23.669,-17.395 cw(c23.906,-19.998) 26.332,-19.027
  lines w0.3: 12.461,-29.686 14.797,-29.686 ; 32.222,-33.776 32.222,-13.776 ; 32.222,-28.776 92.222,-28.776 ; 32.222,-23.776 92.222,-23.776 ; 32.222,-18.776 92.222,-18.776 ; 52.222,-33.776 52.222,-18.776 ; 2.222,-33.776 92.222,-33.776 92.222,-13.776 2.222,-13.776 2.222,-33.776
  text "Project: '.Board_Name'" at 91.028,-16.992 h3
  text "Gerber:" at 51.039,-22.076 h3
  text "Layer:" at 91.028,-22.076 h3
  text "Ref: '.Board_Reference'" at 51.039,-27.076 h3
  text "Variant: '.VariantName'" at 91.028,-27.076 h3
  text "R" at 5.913,-29.559 h1.52
  text "Rev: '.Board_PCB_Revision'" at 51.096,-32.076 h3
  text "Date: '.Board_Document_Date'" at 91.028,-32.076 h3

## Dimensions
1.914,34.101 to 1.922,0.056 on Mechanical 1
1.938,34.125 to 63.427,34.125 on Mechanical 1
